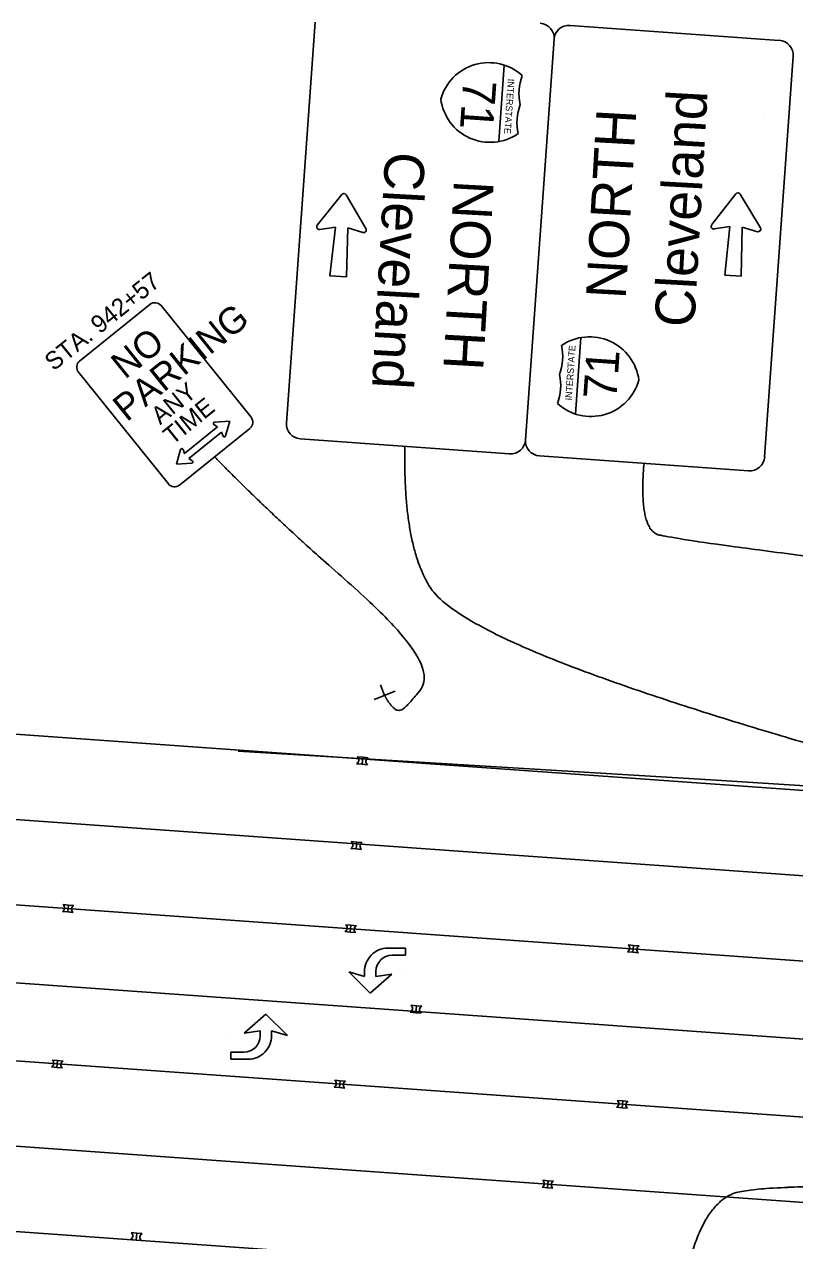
# Model space of a CAD drawing. Extents: x 1847379 to 1850904, y 217032 to 220169.
# Drawn here: x 1849335.9 to 1849444.7, y 218788.3 to 218960 of the extents above; entities that cross this region are included whole.
import ezdxf

# ---------------------------------------------------------------- set-up
doc = ezdxf.new("R2010")
doc.units = 0
for name, color, linetype in [('BR_P_Gen_Approach_Slab_Hidden', 7, 'Continuous'), ('PM_P_Cells', 7, 'Continuous'), ('PM_P_Channelizing_Line', 7, 'Continuous'), ('PM_P_CL_Double_Solid', 7, 'Continuous'), ('PM_P_Edge_Line', 7, 'Continuous'), ('PM_P_Lane_Line', 7, 'Continuous'), ('PM_X_Cells', 7, 'Continuous'), ('PM_X_Surveyed_Line', 7, 'Continuous'), ('SN_X_Public', 7, 'Continuous'), ('SN_X_Text', 7, 'Continuous')]:
    doc.layers.add(name, color=color, linetype=linetype)

msp = doc.modelspace()

# ---------------------------------------------------------------- linework, layer by layer
at = {"layer": 'BR_P_Gen_Approach_Slab_Hidden'}
msp.add_lwpolyline([(1849366.15, 218857.41), (1849433.63, 218853.3), (1849498.54, 218849.15), (1849498.58, 218849.37), (1849508.29, 218861.54), (1849514.81, 218874.18), (1849518.45, 218897.75), (1849514.45, 218923.71), (1849508.93, 218944.96), (1849493.36, 218997.12), (1849479.33, 219045.76), (1849461.72, 219105.45), (1849446.36, 219158.7), (1849432.03, 219205.83)], dxfattribs=at)
at = {"layer": 'PM_P_Cells'}
for p, q in [((1849383.73, 218856.53), (1849382.96, 218856.59)), ((1849382.96, 218856.59), (1849383.73, 218856.53)), ((1849383.64, 218855.55), (1849383.73, 218856.53)), ((1849383.73, 218856.53), (1849384.5, 218856.46)), ((1849382.87, 218855.62), (1849383.64, 218855.55)), ((1849382.87, 218855.62), (1849383.64, 218855.55)), ((1849383.64, 218855.55), (1849384.41, 218855.48)), ((1849382.89, 218844.55), (1849382.12, 218844.62)), ((1849382.12, 218844.62), (1849382.89, 218844.55)), ((1849382.8, 218843.58), (1849382.89, 218844.55)), ((1849382.89, 218844.55), (1849383.66, 218844.48)), ((1849382.04, 218843.65), (1849382.8, 218843.58)), ((1849382.04, 218843.65), (1849382.8, 218843.58)), ((1849382.8, 218843.58), (1849383.57, 218843.51)), ((1849341.32, 218834.76), (1849342.08, 218834.69)), ((1849341.32, 218834.76), (1849342.08, 218834.69)), ((1849342.17, 218835.66), (1849341.41, 218835.73)), ((1849341.41, 218835.73), (1849342.17, 218835.66)), ((1849342.08, 218834.69), (1849342.17, 218835.66)), ((1849342.08, 218834.69), (1849342.85, 218834.62)), ((1849342.17, 218835.66), (1849342.94, 218835.59)), ((1849382.07, 218832.82), (1849381.3, 218832.89)), ((1849381.3, 218832.89), (1849382.07, 218832.82)), ((1849381.98, 218831.84), (1849382.07, 218832.82)), ((1849382.07, 218832.82), (1849382.84, 218832.75)), ((1849381.22, 218831.91), (1849381.98, 218831.84)), ((1849381.22, 218831.91), (1849381.98, 218831.84)), ((1849381.98, 218831.84), (1849382.75, 218831.77)), ((1849389.75, 218829.59), (1849387.27, 218829.59)), ((1849389.75, 218828.59), (1849389.75, 218829.59)), ((1849421.11, 218829.07), (1849421.88, 218829)), ((1849421.11, 218829.07), (1849421.88, 218829)), ((1849421.97, 218829.97), (1849421.2, 218830.04)), ((1849421.2, 218830.04), (1849421.97, 218829.97)), ((1849421.88, 218829), (1849421.97, 218829.97)), ((1849421.88, 218829), (1849422.65, 218828.93)), ((1849421.97, 218829.97), (1849422.74, 218829.9)), ((1849387.89, 218828.59), (1849389.75, 218828.59)), ((1849381.75, 218826.25), (1849381.75, 218826.25)), ((1849383.99, 218825.59), (1849381.75, 218826.25)), ((1849381.75, 218826.25), (1849384.79, 218823.25)), ((1849383.99, 218826.25), (1849383.99, 218825.59)), ((1849384.79, 218823.25), (1849387.83, 218825.92)), ((1849385.59, 218825.59), (1849385.59, 218826.29)), ((1849387.83, 218825.92), (1849385.59, 218825.59)), ((1849389.75, 218826.25), (1849389.75, 218826.25)), ((1849390.45, 218820.54), (1849391.21, 218820.47)), ((1849390.45, 218820.54), (1849391.21, 218820.47)), ((1849391.3, 218821.44), (1849390.53, 218821.51)), ((1849390.53, 218821.51), (1849391.3, 218821.44)), ((1849391.21, 218820.47), (1849391.3, 218821.44)), ((1849391.21, 218820.47), (1849391.98, 218820.4)), ((1849391.3, 218821.44), (1849392.07, 218821.37)), ((1849370.05, 218820.24), (1849367.01, 218817.57)), ((1849373.09, 218817.24), (1849370.05, 218820.24)), ((1849365.09, 218817.24), (1849365.09, 218817.24)), ((1849367.01, 218817.57), (1849369.25, 218817.9)), ((1849369.25, 218817.9), (1849369.25, 218817.2)), ((1849370.85, 218817.24), (1849370.85, 218817.9)), ((1849370.85, 218817.9), (1849373.09, 218817.24)), ((1849373.09, 218817.24), (1849373.09, 218817.24)), ((1849340.64, 218813.72), (1849339.87, 218813.79)), ((1849339.87, 218813.79), (1849340.64, 218813.72)), ((1849340.55, 218812.74), (1849340.64, 218813.72)), ((1849340.64, 218813.72), (1849341.41, 218813.65)), ((1849366.95, 218814.9), (1849365.09, 218814.9)), ((1849365.09, 218814.9), (1849365.09, 218813.9)), ((1849365.09, 218813.9), (1849367.56, 218813.9)), ((1849339.78, 218812.81), (1849340.55, 218812.74)), ((1849339.78, 218812.81), (1849340.55, 218812.74)), ((1849340.55, 218812.74), (1849341.32, 218812.68)), ((1849380.54, 218810.87), (1849379.77, 218810.94)), ((1849379.77, 218810.94), (1849380.54, 218810.87)), ((1849380.45, 218809.9), (1849380.54, 218810.87)), ((1849380.54, 218810.87), (1849381.3, 218810.8)), ((1849379.68, 218809.97), (1849380.45, 218809.9)), ((1849379.68, 218809.97), (1849380.45, 218809.9)), ((1849380.45, 218809.9), (1849381.22, 218809.83)), ((1849419.58, 218807.12), (1849420.35, 218807.05)), ((1849419.58, 218807.12), (1849420.35, 218807.05)), ((1849420.44, 218808.02), (1849419.67, 218808.09)), ((1849419.67, 218808.09), (1849420.44, 218808.02)), ((1849420.35, 218807.05), (1849420.44, 218808.02)), ((1849420.35, 218807.05), (1849421.11, 218806.98)), ((1849420.44, 218808.02), (1849421.2, 218807.95)), ((1849409.9, 218796.74), (1849409.14, 218796.81)), ((1849409.14, 218796.81), (1849409.9, 218796.74)), ((1849409.82, 218795.77), (1849409.9, 218796.74)), ((1849409.9, 218796.74), (1849410.67, 218796.67)), ((1849409.05, 218795.84), (1849409.82, 218795.77)), ((1849409.05, 218795.84), (1849409.82, 218795.77)), ((1849409.82, 218795.77), (1849410.58, 218795.7)), ((1849351.82, 218789.35), (1849351.05, 218789.42)), ((1849351.05, 218789.42), (1849351.82, 218789.35)), ((1849350.96, 218788.44), (1849351.73, 218788.38)), ((1849350.96, 218788.44), (1849351.73, 218788.38)), ((1849351.73, 218788.38), (1849351.82, 218789.35)), ((1849351.73, 218788.38), (1849352.5, 218788.31)), ((1849351.82, 218789.35), (1849352.58, 218789.28))]:
    msp.add_line(p, q, dxfattribs=at)
for centre, radius, start, end in [((1849382.61, 218856.14), 0.576, 296.8063, 52.8586), ((1849382.61, 218856.14), 0.576, 296.8063, 52.8586), ((1849384.76, 218855.94), 0.576, 116.8063, 232.8586), ((1849381.78, 218844.16), 0.576, 296.8063, 52.8586), ((1849381.78, 218844.16), 0.576, 296.8063, 52.8586), ((1849383.92, 218843.97), 0.576, 116.8063, 232.8586), ((1849341.06, 218835.27), 0.576, 296.8063, 52.8586), ((1849341.06, 218835.27), 0.576, 296.8063, 52.8586), ((1849343.2, 218835.08), 0.576, 116.8063, 232.8586), ((1849380.96, 218832.43), 0.576, 296.8063, 52.8586), ((1849380.96, 218832.43), 0.576, 296.8063, 52.8586), ((1849383.1, 218832.23), 0.576, 116.8063, 232.8586), ((1849387.27, 218826.3), 3.28, 90, 180.9085), ((1849420.85, 218829.58), 0.576, 296.8063, 52.8586), ((1849420.85, 218829.58), 0.576, 296.8063, 52.8586), ((1849423, 218829.39), 0.576, 116.8063, 232.8586), ((1849387.89, 218826.29), 2.3, 90, 180), ((1849390.19, 218821.05), 0.576, 296.8063, 52.8586), ((1849390.19, 218821.05), 0.576, 296.8063, 52.8586), ((1849392.33, 218820.86), 0.576, 116.8063, 232.8586), ((1849366.95, 218817.2), 2.3, 270, 360), ((1849367.56, 218817.18), 3.28, 270, 0.9085), ((1849339.52, 218813.33), 0.576, 296.8063, 52.8586), ((1849339.52, 218813.33), 0.576, 296.8063, 52.8586), ((1849341.67, 218813.13), 0.576, 116.8063, 232.8586), ((1849379.42, 218810.48), 0.576, 296.8063, 52.8586), ((1849379.42, 218810.48), 0.576, 296.8063, 52.8586), ((1849381.56, 218810.29), 0.576, 116.8063, 232.8586), ((1849419.32, 218807.63), 0.576, 296.8063, 52.8586), ((1849419.32, 218807.63), 0.576, 296.8063, 52.8586), ((1849421.46, 218807.44), 0.576, 116.8063, 232.8586), ((1849408.79, 218796.35), 0.576, 296.8063, 52.8586), ((1849408.79, 218796.35), 0.576, 296.8063, 52.8586), ((1849410.93, 218796.16), 0.576, 116.8063, 232.8586), ((1849350.7, 218788.96), 0.576, 296.8063, 52.8586), ((1849350.7, 218788.96), 0.576, 296.8063, 52.8586), ((1849352.84, 218788.76), 0.576, 116.8063, 232.8586)]:
    msp.add_arc(centre, radius, start, end, dxfattribs=at)
at = {"layer": 'PM_P_Channelizing_Line'}
for p, q in [((1848983.04, 218860.81), (1849486.82, 218824.85)), ((1848991.59, 218838.14), (1849494.91, 218802.22))]:
    msp.add_line(p, q, dxfattribs=at)
at = {"layer": 'PM_P_CL_Double_Solid'}
msp.add_line((1848992.25, 218849.12), (1849486.03, 218813.88), dxfattribs=at)
at = {"layer": 'PM_P_Edge_Line'}
for p, q in [((1848960.09, 218886.51), (1849497.6, 218848.14)), ((1848953.55, 218816.79), (1849519.44, 218776.41))]:
    msp.add_line(p, q, dxfattribs=at)
at = {"layer": 'PM_P_Lane_Line'}
for p, q in [((1848983.9, 218872.78), (1849487.67, 218836.82)), ((1848990.62, 218826.18), (1849494.05, 218790.25))]:
    msp.add_line(p, q, dxfattribs=at)
at = {"layer": 'PM_X_Cells'}
for p, q in [((1849370.05, 218820.24), (1849367.01, 218817.57)), ((1849373.09, 218817.24), (1849370.05, 218820.24)), ((1849365.09, 218817.24), (1849365.09, 218817.24)), ((1849367.01, 218817.57), (1849369.25, 218817.9)), ((1849369.25, 218817.9), (1849369.25, 218817.2)), ((1849370.85, 218817.24), (1849370.85, 218817.9)), ((1849370.85, 218817.9), (1849373.09, 218817.24)), ((1849373.09, 218817.24), (1849373.09, 218817.24)), ((1849366.95, 218814.9), (1849365.09, 218814.9)), ((1849365.09, 218814.9), (1849365.09, 218813.9)), ((1849365.09, 218813.9), (1849367.56, 218813.9))]:
    msp.add_line(p, q, dxfattribs=at)
for centre, radius, end in [((1849366.95, 218817.2), 2.3, 0), ((1849367.56, 218817.18), 3.28, 0.9085)]:
    msp.add_arc(centre, radius, 270, end, dxfattribs=at)
at = {"layer": 'PM_X_Surveyed_Line'}
msp.add_line((1849363, 218822.43), (1849363, 218822.43), dxfattribs=at)
at = {"layer": 'SN_X_Public'}
for p, q in [((1849403.72, 218954.23), (1849402.97, 218943.44)), ((1849440.46, 218947.43), (1849440.46, 218947.43)), ((1849377.32, 218931.64), (1849380.76, 218935.97)), ((1849381.37, 218935.93), (1849384.18, 218931.16)), ((1849433.01, 218931.71), (1849436.42, 218936.07)), ((1849437.03, 218936.03), (1849439.88, 218931.28)), ((1849379.87, 218931.37), (1849377.67, 218931.03)), ((1849379.1, 218924.5), (1849379.87, 218931.37)), ((1849381.62, 218931.25), (1849381.43, 218924.34)), ((1849383.75, 218930.61), (1849381.62, 218931.25)), ((1849435.56, 218931.46), (1849433.37, 218931.1)), ((1849434.85, 218924.58), (1849435.56, 218931.46)), ((1849437.32, 218931.35), (1849437.18, 218924.43)), ((1849439.45, 218930.72), (1849437.32, 218931.35)), ((1849381.43, 218924.34), (1849379.1, 218924.5)), ((1849437.18, 218924.43), (1849434.85, 218924.58)), ((1849413.76, 218904.98), (1849414.51, 218915.77)), ((1849363.21, 218903.15), (1849358.58, 218899.42)), ((1849362.72, 218903.48), (1849363.21, 218903.15)), ((1849364.96, 218903.96), (1849362.8, 218903.82)), ((1849363.21, 218903.15), (1849363.21, 218903.15)), ((1849364.36, 218901.88), (1849364.96, 218903.96)), ((1849363.8, 218902.42), (1849364.02, 218901.86)), ((1849358.02, 218899.96), (1849357.42, 218897.88)), ((1849358.58, 218899.42), (1849358.36, 218899.97)), ((1849358.58, 218899.42), (1849358.59, 218899.42)), ((1849361.38, 218900.7), (1849361.38, 218900.7)), ((1849357.42, 218897.88), (1849359.58, 218898.02)), ((1849359.67, 218898.36), (1849359.17, 218898.69)), ((1849386.82, 218865.26), (1849386.22, 218866.74)), ((1849388.3, 218865.86), (1849385.33, 218864.66))]:
    msp.add_line(p, q, dxfattribs=at)
for points in [[(1849372.96, 218903.74), (1849377, 218960.28)], [(1849413.01, 218959.84), (1849442.55, 218957.73)], [(1849410.75, 218957.88), (1849406.72, 218901.33)], [(1849406.72, 218901.33), (1849410.75, 218957.88)], [(1849444.51, 218955.47), (1849440.48, 218898.93)], [(1849353.68, 218920.46), (1849343.75, 218912.46)], [(1849367.97, 218904.52), (1849355.26, 218920.29)], [(1849343.58, 218910.88), (1849356.29, 218895.11)], [(1849357.87, 218894.94), (1849367.8, 218902.94)], [(1849359.17, 218898.69), (1849363.8, 218902.42)], [(1849404.46, 218899.37), (1849374.92, 218901.48)], [(1849438.22, 218896.97), (1849408.68, 218899.07)]]:
    msp.add_lwpolyline(points, dxfattribs=at)
for centre, radius, start, end in [((1849408.64, 218958.03), 2.12, 355.9213, 85.9213), ((1849412.86, 218957.73), 2.12, 85.9213, 175.9213), ((1849442.4, 218955.62), 2.12, 355.9213, 85.9213), ((1849401.52, 218947.55), 7.03, 47.7054, 164.4995), ((1849412.82, 218950.24), 7.03, 159.0455, 193.0274), ((1849401.72, 218950.36), 7.03, 187.5734, 304.3675), ((1849412.54, 218946.14), 7.03, 159.0455, 193.0274), ((1849381.05, 218935.73), 0.38, 31.9428, 140.1301), ((1849436.71, 218935.82), 0.38, 32.3812, 140.5685), ((1849377.61, 218931.4), 0.38, 141.5393, 279.0126), ((1849383.86, 218930.97), 0.38, 253.0602, 30.5335), ((1849433.31, 218931.47), 0.38, 141.9777, 279.4511), ((1849439.56, 218931.09), 0.38, 253.4986, 30.9719), ((1849354.38, 218919.58), 1.12, 38.8676, 128.8676), ((1849415.76, 218908.85), 7.03, 7.5734, 124.3675), ((1849404.94, 218913.07), 7.03, 339.0455, 13.0274), ((1849344.46, 218911.58), 1.12, 128.8676, 218.8676), ((1849404.65, 218908.97), 7.03, 339.0455, 13.0274), ((1849415.95, 218911.66), 7.03, 227.7054, 344.4995), ((1849367.09, 218903.82), 1.12, 308.8676, 38.8676), ((1849362.82, 218903.63), 0.182, 93.7884, 236.5054), ((1849375.07, 218903.59), 2.12, 175.9213, 265.9213), ((1849364.19, 218901.93), 0.182, 201.2298, 343.9469), ((1849404.61, 218901.48), 2.12, 265.9213, 355.9213), ((1849408.83, 218901.18), 2.12, 175.9213, 265.9213), ((1849358.19, 218899.91), 0.182, 21.2298, 163.9469), ((1849359.57, 218898.21), 0.182, 273.7884, 56.5054), ((1849438.37, 218899.08), 2.12, 265.9213, 355.9213), ((1849357.16, 218895.82), 1.12, 218.8676, 308.8676)]:
    msp.add_arc(centre, radius, start, end, dxfattribs=at)
for points in [[(1849472.07, 218852.11), (1849451.23, 218856.4), (1849396.9, 218874.53), (1849389.39, 218886.8), (1849389.69, 218900.43)], [(1849386.82, 218865.26), (1849387.72, 218863.54), (1849389.52, 218862.77), (1849394.48, 218869.94), (1849370.3, 218891.18), (1849362.83, 218898.94)], [(1849474.07, 218851.97), (1849477.47, 218852.18), (1849478.91, 218858.87), (1849477.85, 218871.18), (1849466.81, 218882.25), (1849428.48, 218887.21), (1849422.66, 218888.6), (1849423.45, 218898.02)]]:
    msp.add_open_spline(points, degree=2, dxfattribs=at)
at = {"layer": 'SN_X_Text'}
msp.add_open_spline([(1849494.67, 218818.75), (1849500.66, 218818.68), (1849506.53, 218812.81), (1849502.68, 218794.1), (1849444.39, 218796.58), (1849429.74, 218793.85), (1849428.09, 218773.83)], degree=2, dxfattribs=at)

# ---------------------------------------------------------------- texts
at = {"layer": 'SN_X_Public'}
for s, height, rotation, p in [('71', 4.688, 266.0364, (1849397.94, 218952.25)), ('INTERSTATE', 0.937, 266.0364, (1849404.23, 218952.33)), ('Cleveland', 5.625, 86.7692, (1849430.54, 218917.13)), ('NORTH', 5.625, 86.7692, (1849420.86, 218921.14)), ('Cleveland', 5.625, 266.7692, (1849386.93, 218942.08)), ('NORTH', 5.625, 266.7692, (1849396.62, 218938.07)), ('STA. 942+57', 2.5, 38.8676, (1849340.09, 218910.97)), ('PARKING', 3.75, 38.8676, (1849350.41, 218903.78)), ('NO', 3.75, 38.8676, (1849350.16, 218909.8)), ('INTERSTATE', 0.937, 86.0364, (1849413.25, 218906.88)), ('71', 4.688, 86.0364, (1849419.54, 218906.95)), ('ANY', 2.5, 38.8676, (1849355.13, 218903.37)), ('TIME', 2.5, 38.8676, (1849356.84, 218900.53))]:
    msp.add_text(s, height=height, rotation=rotation, dxfattribs=at).set_placement(p)

doc.saveas('drawing.dxf')
